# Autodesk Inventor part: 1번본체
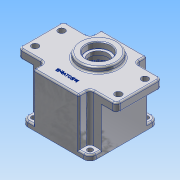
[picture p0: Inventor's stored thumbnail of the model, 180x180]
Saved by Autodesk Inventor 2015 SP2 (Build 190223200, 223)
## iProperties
Created: 2015-06
Part Number: 1번본체
Material: 알루미늄 6061
Document SubType Name: Modeling
Designer: AMC
Density: 2.7 g/cm^3
Appearance: 알루미늄 - 평지
Mass: 704.51 g
Surface Area: 673.549 cm^2
Volume: 260.93 cm^3
Author: AMC
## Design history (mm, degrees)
sketch "스케치5"
  geometry: L1 (0, 0)-(90, 0); L2 (90, 0)-(90, 90); L3 (90, 90)-(0, 90); L4 (0, 90)-(0, 0)
  constraints: 8 end point, 2 parallel, 1 horizontal, 1 perpendicular
  dimensions: "d29" = 90 distance of L2.end L3.end; "d30" = 90 distance of L3.end L1.start
extrude "돌출5" new body sketch "스케치5" distance "d31" = 70; taper "d32" = 0 deg
sketch "스케치6"
  geometry: L1 (0, 90)-(15, 90); L2 (15, 90)-(15, 75); L3 (15, 75)-(0, 75); L4 (0, 75)-(0, 90); L5 (90, 90)-(75, 90); L6 (75, 90)-(75, 75); L7 (75, 75)-(90, 75); L8 (90, 75)-(90, 90); L9 (0, 90)-(0, 0) reference; L10 (0, 45)-(20.47, 45); L11 (15, 0)-(15, 15); L12 (15, 15)-(0, 15); L13 (0, 0)-(15, 0); L14 (0, 15)-(0, 0); L15 (75, 0)-(75, 15); L16 (75, 15)-(90, 15); L17 (90, 15)-(90, 0); L18 (90, 0)-(75, 0)
  constraints: 34 end point, 7 symmetric about line, 4 parallel, 3 horizontal, 2 perpendicular, 2 point on line, 1 midpoint
  dimensions: "d40" = 15 distance of L2.end L3.end; "d41" = 15 distance of L1.end L2.end; "d42" = 15 distance of L5.start L5.end
extrude "돌출6" cut sketch "스케치6" distance "d43" = 63; taper "d44" = 0 deg
sketch "스케치7"
  geometry: L1 (-20, 75)-(110, 75); L2 (110, 75)-(110, 15); L3 (110, 15)-(-20, 15); L4 (-20, 15)-(-20, 75); L5 (15, 75)-(0, 75) reference; L6 (75, 15)-(90, 15) reference; L7 (90, 15)-(75, 15) reference; L8 (75, 15)-(75, 0) reference; L9 (75, 0)-(15, 0) reference; L10 (15, 0)-(15, 15) reference; L11 (15, 15)-(0, 15) reference; L12 (0, 15)-(0, 75) reference; L13 (0, 75)-(15, 75) reference; L14 (15, 75)-(15, 90) reference; L15 (15, 90)-(75, 90) reference; L16 (75, 90)-(75, 75) reference; L17 (75, 75)-(90, 75) reference; L18 (90, 75)-(90, 15) reference; 5 further points
  constraints: 8 end point, 4 midpoint, 2 collinear, 2 parallel, 2 vertical alignment, 1 horizontal, 1 perpendicular
  dimensions: "d45" = 130 distance of L1.start L1.end
extrude "돌출7" join sketch "스케치7" distance "d46" = 12; taper "d47" = 0 deg
sketch "스케치8"
  geometry: L1 (75, 90)-(75, 75) reference; L2 (75, 75)-(110, 75) reference; L3 (110, 75)-(110, 15) reference; L4 (110, 15)-(75, 15) reference; L5 (75, 15)-(75, 0) reference; L6 (75, 0)-(15, 0) reference; L7 (15, 0)-(15, 15) reference; L8 (15, 15)-(-20, 15) reference; L9 (-20, 15)-(-20, 75) reference; L10 (-20, 75)-(15, 75) reference; L11 (15, 75)-(15, 90) reference; L12 (15, 90)-(75, 90) reference; L13 (110, 75)-(110, 15) reference; C1 r 25 at (45, 56); 3 further points
  constraints: 2 midpoint, 1 centre point, 1 vertical alignment
  dimensions: "d48" = 50 diameter of C1; "d62" = 11 vertical distance of point (110, 45) C1.centre
extrude "돌출8" join sketch "스케치8" distance "d49" = 7; taper "d50" = 0 deg
fillet "모깎기3" dims "d51" = 5
fillet "모깎기4" dims "d52" = 2
node "작업 평면1"
fillet "모깎기5" dims "d76" = 8
fillet "모깎기6" dims "d102" = 2
fillet "모깎기7" dims "d103" = 2
sketch "스케치17"
  geometry: L1 (90, 82)-(90, 75) reference; L2 (90, 75)-(90, 15) reference; L3 (90, 15)-(90, 8) reference; L4 (82, 0)-(73, 0) reference; L5 (73, 0)-(17, 0) reference; L6 (17, 0)-(8, 0) reference; L7 (0, 8)-(0, 15) reference; L8 (0, 15)-(0, 75) reference; L9 (0, 75)-(10, 75) reference; L10 (15, 80)-(15, 88) reference; L11 (8, 90)-(17, 90) reference; L12 (0, 75)-(0, 82) reference; L13 (73, 90)-(82, 90) reference; L14 (75, 88)-(75, 80) reference; L15 (80, 75)-(90, 75) reference; L16 (90, 15)-(80, 15) reference; L17 (75, 10)-(75, 2) reference; L18 (15, 2)-(15, 10) reference; L19 (10, 15)-(0, 15) reference; L20 (17, 90)-(73, 90) reference; A1 r 8 centre (82, 8) between (82, 0) and (90, 8) reference; A2 r 8 centre (8, 8) between (0, 8) and (8, 0) reference; A3 r 5 centre (10, 80) between (10, 75) and (15, 80) reference; A4 r 2 centre (17, 88) between (17, 90) and (15, 88) reference; A5 r 8 centre (8, 82) between (8, 90) and (0, 82) reference; A6 r 8 centre (82, 82) between (90, 82) and (82, 90) reference; A7 r 2 centre (73, 88) between (75, 88) and (73, 90) reference; A8 r 5 centre (80, 80) between (75, 80) and (80, 75) reference; A9 r 5 centre (80, 10) between (80, 15) and (75, 10) reference; A10 r 2 centre (73, 2) between (73, 0) and (75, 2) reference; A11 r 2 centre (17, 2) between (15, 2) and (17, 0) reference; A12 r 5 centre (10, 10) between (15, 10) and (10, 15) reference; 5 further points
  constraints: 4 coincident
hole "구멍2" sketch "스케치17" at (8, 82), (8, 8), (82, 82), (82, 8) diameter "d104" = 7; stored, may be unused: countersink angle "d108" = 90 deg, drill point angle "d110" = 118 deg; dims "d105" = 12, "d106" = 4, "d107" = 2, "d109" = 15
sketch "스케치18"
  geometry: L1 (73, 80)-(73, 88) reference; L2 (17, 88)-(17, 80) reference; L3 (-15, 73)-(10, 73) reference; L4 (-18, 20)-(-18, 70) reference; L5 (-15, 17)-(10, 17) reference; L6 (17, 10)-(17, 2) reference; L7 (73, 2)-(73, 10) reference; L8 (105, 17)-(80, 17) reference; L9 (108, 70)-(108, 20) reference; L10 (105, 73)-(80, 73) reference; L11 (-30.692, 45)-(122.737, 45); L12 (17, 2)-(73, 2) reference; L13 (73, 88)-(17, 88) reference; C1 r 27 at (45, 56) reference; C2 r 4.5 at (-10, 62.5); C3 r 4.5 at (-10, 27.5); C4 r 4.5 at (100, 62.5); C5 r 4.5 at (100, 27.5); A1 r 7 centre (10, 80) between (10, 73) and (17, 80) reference; A2 r 3 centre (-15, 70) between (-15, 73) and (-18, 70) reference; A3 r 3 centre (-15, 20) between (-18, 20) and (-15, 17) reference; A4 r 7 centre (10, 10) between (17, 10) and (10, 17) reference; A5 r 7 centre (80, 10) between (80, 17) and (73, 10) reference; A6 r 3 centre (105, 20) between (105, 17) and (108, 20) reference; A7 r 3 centre (105, 70) between (108, 70) and (105, 73) reference; A8 r 7 centre (80, 80) between (73, 80) and (80, 73) reference; 2 further points
  constraints: 4 centre point, 2 end point, 2 equal radius, 2 horizontal alignment, 2 vertical alignment, 1 midpoint, 1 perpendicular, 1 point on line
  dimensions: "d116" = 110 distance of C2.centre C4.centre; "d117" = 35 distance of C5.centre C4.centre; "d118" = 55 horizontal distance of C1.centre C4.centre; "d119" = 17.5 distance from line of L11 C2.centre; "d120" = 9 diameter of C2; "d121" = 9 diameter of C4
extrude "돌출14" cut sketch "스케치18" stored distance "d122" = 45; taper "d123" = 0 deg
sketch "스케치19"
  geometry: L1 (-8, 0)-(-82, 0) reference; L2 (-90, 8)-(-90, 82) reference; L3 (-82, 90)-(-8, 90) reference; L4 (0, 82)-(0, 8) reference; C1 r 3.5 at (-82, 82) reference; C2 r 3.5 at (-8, 82) reference; C3 r 3.5 at (-8, 8) reference; C4 r 3.5 at (-82, 8) reference; C5 r 40 at (-45, 45); A1 r 8 centre (-82, 8) between (-90, 8) and (-82, 0) reference; A2 r 8 centre (-82, 82) between (-82, 90) and (-90, 82) reference; A3 r 8 centre (-8, 82) between (0, 82) and (-8, 90) reference; A4 r 8 centre (-8, 8) between (-8, 0) and (0, 8) reference; 3 further points
  constraints: 2 midpoint, 1 centre point, 1 horizontal alignment, 1 vertical alignment
  dimensions: "d124" = 80 diameter of C5
extrude "돌출15" cut sketch "스케치19" distance "d125" = 9; taper "d126" = 0 deg
sketch "스케치20"
  geometry: L1 (-45, -30)-(-45, 30) reference; L2 (-30, 35)-(-30, 43) reference; L3 (-28, 45)-(28, 45) reference; L4 (30, 43)-(30, 35) reference; L5 (35, 30)-(45, 30) reference; L6 (45, 30)-(45, -30) reference; L7 (45, -30)-(35, -30) reference; L8 (30, -35)-(30, -43) reference; L9 (28, -45)-(-28, -45) reference; L10 (-30, -43)-(-30, -35) reference; L11 (-35, -30)-(-45, -30) reference; L12 (-45, 30)-(-35, 30) reference; C1 r 39 at (0, 0); C2 r 40 at (0, 0) reference; A1 r 5 centre (-35, -35) between (-30, -35) and (-35, -30) reference; A2 r 5 centre (-35, 35) between (-35, 30) and (-30, 35) reference; A3 r 2 centre (-28, 43) between (-28, 45) and (-30, 43) reference; A4 r 2 centre (28, 43) between (30, 43) and (28, 45) reference; A5 r 5 centre (35, 35) between (30, 35) and (35, 30) reference; A6 r 5 centre (35, -35) between (35, -30) and (30, -35) reference; A7 r 2 centre (28, -43) between (28, -45) and (30, -43) reference; A8 r 2 centre (-28, -43) between (-30, -43) and (-28, -45) reference; 1 further point
  constraints: 1 centre point, 1 coincident
  dimensions: "d127" = 78 diameter of C1
extrude "돌출16" cut sketch "스케치20" distance "d128" = 52; taper "d129" = 0 deg
sketch "스케치21"
  geometry: L1 (-65, -25)-(-65, 25) reference; L2 (-30, 35)-(-30, 43) reference; L3 (-28, 45)-(28, 45) reference; L4 (30, 43)-(30, 35) reference; L5 (35, 30)-(60, 30) reference; L6 (65, 25)-(65, -25) reference; L7 (60, -30)-(35, -30) reference; L8 (30, -35)-(30, -43) reference; L9 (28, -45)-(-28, -45) reference; L10 (-30, -43)-(-30, -35) reference; L11 (-35, -30)-(-60, -30) reference; L12 (-60, 30)-(-35, 30) reference; C1 r 39 at (0, 0) reference; C2 r 4.5 at (-55, 17.5) reference; C3 r 4.5 at (-55, -17.5) reference; C4 r 4.5 at (55, -17.5) reference; C5 r 4.5 at (55, 17.5) reference; A1 r 5 centre (-35, -35) between (-30, -35) and (-35, -30) reference; A2 r 5 centre (-60, -25) between (-65, -25) and (-60, -30) reference; A3 r 5 centre (-60, 25) between (-60, 30) and (-65, 25) reference; A4 r 5 centre (-35, 35) between (-35, 30) and (-30, 35) reference; A5 r 2 centre (-28, 43) between (-28, 45) and (-30, 43) reference; A6 r 2 centre (28, 43) between (30, 43) and (28, 45) reference; A7 r 5 centre (35, 35) between (30, 35) and (35, 30) reference; A8 r 5 centre (60, 25) between (65, 25) and (60, 30) reference; A9 r 5 centre (60, -25) between (60, -30) and (65, -25) reference; A10 r 5 centre (35, -35) between (35, -30) and (30, -35) reference; A11 r 2 centre (28, -43) between (28, -45) and (30, -43) reference; A12 r 2 centre (-28, -43) between (-30, -43) and (-28, -45) reference; A13 r 20.5 centre (0, 11) between (7.402, -8.117) and (-7.402, -8.117); A14 r 14 centre (0, -20) between (-7.402, -8.117) and (7.402, -8.117); 1 further point
  constraints: 4 point on circle, 2 centre point, 2 vertical alignment
  dimensions: "d130" = 41 diameter of A13; "d131" = 28 diameter of A14; "d132" = 20 distance of A14.centre C1.centre; "d133" = 11 distance of C1.centre A13.centre
extrude "돌출17" join sketch "스케치21" distance "d134" = 7; taper "d135" = 0 deg
node "작업 평면2"
sketch "스케치22"
  geometry: L1 (-12, -13)-(-12, 14) reference; L2 (-14, 16)-(-19, 16) reference; L3 (-19, 16)-(-19, 66) reference; L4 (-19, 66)-(-14, 66) reference; L5 (-12, 68)-(-12, 73) reference; L6 (-10, 75)-(58, 75) reference; L7 (58, 75)-(58, 70) reference; L8 (58, 70)-(49, 70) reference; L9 (49, 70)-(49, 69) reference; L10 (49, 69)-(-3, 69) reference; L11 (-3, 69)-(-3, 61.5) reference; L12 (-3, 61.5)-(4, 61.5) reference; L13 (4, 61.5)-(4, -4) reference; L14 (4, -4)-(-3, -4) reference; L15 (-3, -4)-(-3, -9) reference; L16 (-3, -9)-(49, -9) reference; L17 (49, -9)-(49, -10) reference; L18 (49, -10)-(58, -10) reference; L19 (58, -10)-(58, -15) reference; L20 (58, -15)-(-10, -15) reference; L21 (-19, 41)-(18.673, 41); L22 (-19, 66)-(-19, 16) reference; L23 (-19, 57)-(-11, 57); L24 (-12, 68)-(-12, 14) reference; L25 (-11, 53.5)-(-6, 53.5); L26 (-6, 53.5)-(-6, 58.5); L27 (-6, 58.5)-(4, 58.5); L28 (-11, 57)-(-11, 53.5); L29 (4, -4)-(4, 21.883) reference; L30 (58, 67)-(58, -7) reference; L31 (-12, 10)-(62.879, 10); L32 (4, 21)-(-3, 21); L33 (-3, 21)-(-3, 19.5); L34 (-3, 19.5)-(-4, 19.5); L35 (-4, 19.5)-(-4, 10); L36 (-19, 57)-(-19, 41); L37 (4, 21)-(4, 10); L38 (4, 58.5)-(4, 41); A1 r 2 centre (-10, -13) between (-12, -13) and (-10, -15) reference; A2 r 2 centre (-14, 14) between (-12, 14) and (-14, 16) reference; A3 r 2 centre (-14, 68) between (-14, 66) and (-12, 68) reference; A4 r 2 centre (-10, 73) between (-10, 75) and (-12, 73) reference; 1 further point
  constraints: 28 end point, 9 point on line, 8 perpendicular, 3 horizontal, 2 midpoint, 1 collinear
  dimensions: "d136" = 10 distance of L26.end L27.end; "d137" = 8 distance of L23.start L23.end; "d138" = 32 diameter of L23 L21; "d139" = 35 diameter of L27 L21; "d140" = 25 diameter of L25 L21; "d141" = 40 diameter of point (58, 30) L31; "d142" = 19 diameter of L34 L31; "d143" = 22 diameter of L32 L31; "d144" = 7 distance of L32.start L32.end; "d145" = 1 distance of L33.end L34.end
  node "절단 모서리 투영21"
revolve "회전3" stored, may be unused: angle "d146" = 90 deg
revolve "회전4" stored, may be unused: angle "d147" = 90 deg
chamfer "모따기1" distance "d148" = 1; stored, may be unused: second distance "d149" = 2, angle "d150" = 45 deg
fillet "모깎기8" dims "d151" = 3
fillet "모깎기9" dims "d152" = 2
sketch "스케치23" dims "d153" = 70
  geometry: L1 (-45, -30)-(-45, 30) reference; L2 (-30, 35)-(-30, 43) reference; L3 (-28, 45)-(28, 45) reference; L4 (30, 43)-(30, 35) reference; L5 (35, 30)-(45, 30) reference; L6 (45, 30)-(45, -30) reference; L7 (45, -30)-(35, -30) reference; L8 (30, -35)-(30, -43) reference; L9 (28, -45)-(-28, -45) reference; L10 (-30, -43)-(-30, -35) reference; L11 (0, 0)-(0, 55.728); L12 (0, 0)-(58.143, 58.143); L13 (-35, -30)-(-45, -30) reference; L14 (-45, 30)-(-35, 30) reference; C1 r 40 at (0, 0) reference; A1 r 39 centre (0, 0) between (32.777, 21.134) and (21.134, 32.777) reference; A2 r 5 centre (-35, -35) between (-30, -35) and (-35, -30) reference; A3 r 5 centre (-35, 35) between (-35, 30) and (-30, 35) reference; A4 r 2 centre (-28, 43) between (-28, 45) and (-30, 43) reference; A5 r 2 centre (28, 43) between (30, 43) and (28, 45) reference; A6 r 5 centre (35, 35) between (30, 35) and (35, 30) reference; A7 r 5 centre (35, -35) between (35, -30) and (30, -35) reference; A8 r 2 centre (28, -43) between (28, -45) and (30, -43) reference; A9 r 2 centre (-28, -43) between (-30, -43) and (-28, -45) reference; A10 r 4 centre (24.749, 24.749) between (21.809, 27.462) and (27.462, 21.809); A11 r 3.5 centre (29.836, 19.238) between (32.777, 21.134) and (27.462, 21.809); A12 r 3.5 centre (19.238, 29.836) between (21.809, 27.462) and (21.134, 32.777); 1 further point
  constraints: 8 point on circle, 4 end point, 4 tangent, 3 centre point, 1 coincident, 1 point on line, 1 vertical, 3 other
  dimensions: "d154" = 45 deg angle of L11 L12; "d155" = 8 diameter of A10; "d156" = 7 diameter of A11; "d157" = 7 diameter of A12
extrude "돌출18" join sketch "스케치23" stored distance "d158" = 7; taper "d159" = 0 deg
sketch "스케치24"
  geometry: L1 (-45, -30)-(-45, 30) reference; L2 (-30, 35)-(-30, 43) reference; L3 (-28, 45)-(28, 45) reference; L4 (30, 43)-(30, 35) reference; L5 (35, 30)-(45, 30) reference; L6 (45, 30)-(45, -30) reference; L7 (45, -30)-(35, -30) reference; L8 (30, -35)-(30, -43) reference; L9 (28, -45)-(-28, -45) reference; L10 (-30, -43)-(-30, -35) reference; L11 (-35, -30)-(-45, -30) reference; L12 (-45, 30)-(-35, 30) reference; C1 r 40 at (0, 0) reference; A1 r 4 centre (24.749, 24.749) between (21.809, 27.462) and (27.462, 21.809) reference; A2 r 3.5 centre (19.238, 29.836) between (21.809, 27.462) and (21.134, 32.777) reference; A3 r 39 centre (0, 0) between (21.134, 32.777) and (-21.134, 32.777) reference; A4 r 3.5 centre (-19.238, 29.836) between (-21.134, 32.777) and (-21.809, 27.462) reference; A5 r 4 centre (-24.749, 24.749) between (-27.462, 21.809) and (-21.809, 27.462) reference; A6 r 3.5 centre (-29.836, 19.238) between (-27.462, 21.809) and (-32.777, 21.134) reference; A7 r 39 centre (0, 0) between (-32.777, 21.134) and (-32.777, -21.134) reference; A8 r 3.5 centre (-29.836, -19.238) between (-32.777, -21.134) and (-27.462, -21.809) reference; A9 r 4 centre (-24.749, -24.749) between (-21.809, -27.462) and (-27.462, -21.809) reference; A10 r 3.5 centre (-19.238, -29.836) between (-21.809, -27.462) and (-21.134, -32.777) reference; A11 r 39 centre (0, 0) between (-21.134, -32.777) and (21.134, -32.777) reference; A12 r 3.5 centre (19.238, -29.836) between (21.134, -32.777) and (21.809, -27.462) reference; A13 r 4 centre (24.749, -24.749) between (27.462, -21.809) and (21.809, -27.462) reference; A14 r 3.5 centre (29.836, -19.238) between (27.462, -21.809) and (32.777, -21.134) reference; A15 r 39 centre (0, 0) between (32.777, -21.134) and (32.777, 21.134) reference; A16 r 3.5 centre (29.836, 19.238) between (32.777, 21.134) and (27.462, 21.809) reference; A17 r 5 centre (-35, -35) between (-30, -35) and (-35, -30) reference; A18 r 5 centre (-35, 35) between (-35, 30) and (-30, 35) reference; A19 r 2 centre (-28, 43) between (-28, 45) and (-30, 43) reference; A20 r 2 centre (28, 43) between (30, 43) and (28, 45) reference; A21 r 5 centre (35, 35) between (30, 35) and (35, 30) reference; A22 r 5 centre (35, -35) between (35, -30) and (30, -35) reference; A23 r 2 centre (28, -43) between (28, -45) and (30, -43) reference; A24 r 2 centre (-28, -43) between (-30, -43) and (-28, -45) reference; 5 further points
  constraints: 4 coincident
hole "구멍3" sketch "스케치24" at (-24.749, 24.749), (24.749, 24.749), (24.749, -24.749), (-24.749, -24.749) diameter "d163" = 3.242; stored, may be unused: countersink angle "d167" = 90 deg, drill point angle "d169" = 118 deg; dims "d164" = 12, "d165" = 4, "d166" = 2, "d168" = 15
fillet "모깎기10" dims "d170" = 4
fillet "모깎기11" dims "d171" = 0.3
fillet "모깎기12" dims "d172" = 0.3
sketch "스케치26"
  geometry: L1 (17, 88)-(17, 80) reference; L2 (-15, 73)-(10, 73) reference; L3 (-18, 20)-(-18, 70) reference; L4 (-15, 17)-(10, 17) reference; L5 (17, 10)-(17, 2) reference; L6 (17, 2)-(73, 2) reference; L7 (73, 2)-(73, 10) reference; L8 (105, 17)-(80, 17) reference; L9 (108, 70)-(108, 20) reference; L10 (105, 73)-(80, 73) reference; L11 (73, 80)-(73, 88) reference; L12 (73, 88)-(17, 88) reference; L13 (17, 0)-(73, 0) reference; C1 r 16 at (45, 56) reference; C2 r 4.5 at (100, 62.5) reference; C3 r 4.5 at (100, 27.5) reference; C4 r 4.5 at (-10, 27.5) reference; C5 r 4.5 at (-10, 62.5) reference; C6 r 27 at (45, 56) reference; A1 r 7 centre (10, 80) between (10, 73) and (17, 80) reference; A2 r 3 centre (-15, 70) between (-15, 73) and (-18, 70) reference; A3 r 3 centre (-15, 20) between (-18, 20) and (-15, 17) reference; A4 r 7 centre (10, 10) between (17, 10) and (10, 17) reference; A5 r 7 centre (80, 10) between (80, 17) and (73, 10) reference; A6 r 3 centre (105, 20) between (105, 17) and (108, 20) reference; A7 r 3 centre (105, 70) between (108, 70) and (105, 73) reference; A8 r 7 centre (80, 80) between (73, 80) and (80, 73) reference; 2 further points
  constraints: 1 vertical alignment, 1 other
  dimensions: "d176" = 15 distance from line of L13 point (45, 15)
feature "엠보싱2" sketch "스케치26" dims "d40" = 15, "d41" = 15, "d42" = 15, "d177" = 0.5, "d178" = 0
fillet "모깎기13" dims "d179" = 2
fillet "모깎기14" dims "d180" = 2
fillet "모깎기15" dims "d181" = 2
fillet "모깎기16" dims "d182" = 2
fillet "모깎기17" dims "d183" = 2
fillet "모깎기18" dims "d184" = 0.3
node "솔리드2"
pattern_circular "원형 패턴3" dims angle "d161" = 360 deg
node "절단 모서리 투영3"
node "절단 모서리 투영4"
node "절단 모서리 투영16"
node "절단 모서리 투영17"
node "절단 모서리 투영18"
node "절단 모서리 투영19"
node "절단 모서리 투영20"
node "절단 모서리 투영22"
node "절단 모서리 투영23"
node "절단 모서리 투영25"
